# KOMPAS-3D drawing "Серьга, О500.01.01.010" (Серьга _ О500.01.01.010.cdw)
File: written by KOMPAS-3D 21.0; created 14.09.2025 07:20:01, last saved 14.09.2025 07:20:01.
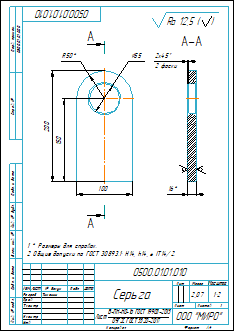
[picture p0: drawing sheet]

Sheet 1: A4, portrait

Document properties: Полное имя файла: C:\Users\Lutik\Yandex.Disk\Документы\Новая папка\Стапель №2\Оправка 500\Оправка _ О500.01.00.000\2D\О500.01.01.000 _ Оправка\Серьга _ О500.01.01.010.cdw; Знак неуказанной шероховатости: 4; Параметр неуказанной шероховатости: Ra 12,5; Масса: 2.073269

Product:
- Part/product: Серьга  | designation О500.01.01.010
    Материал: Лист$dБ-ПН-НО-16 ГОСТ 19903-2015;09Г2С ГОСТ 5520-2017$ (density 7850 kg/m3)
    Масса: 2.073269

Title block, sheet 1: Наименование: Серьга; designation: О500.01.01.010; Материал: Лист Б-ПН-НО-16 ГОСТ 19903-2015 09Г2С ГОСТ 5520-2017; Масса: 2,07; Количество листов документа: 1; organisation: ООО "МИРО"; Форматы листов документа: A4; Разработал: Тимонин

Views: Вид 1, Слева, Разрез А-А
Referenced files in C:\Users\Lutik\Yandex.Disk\Документы\Новая папка\Стапель №2\Оправка 500\Оправка _ О500.01.00.000\3D\Оправка _ О500.01.01.000\: Серьга _ О500.01.01.010.m3d
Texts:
  Ra 12,5
  Ra 12,5 ( )
  О500.01.01.010 Серьга
Dimensions and other numbers on the sheet: 100; 50; 55; 150; 200; 16; 2; 2 фаски; 1:2; 1; 2,07

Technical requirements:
  * Размеры для справок.
  Общие допуски по ГОСТ 30893.1: Н14, h14, ± IT14/2.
